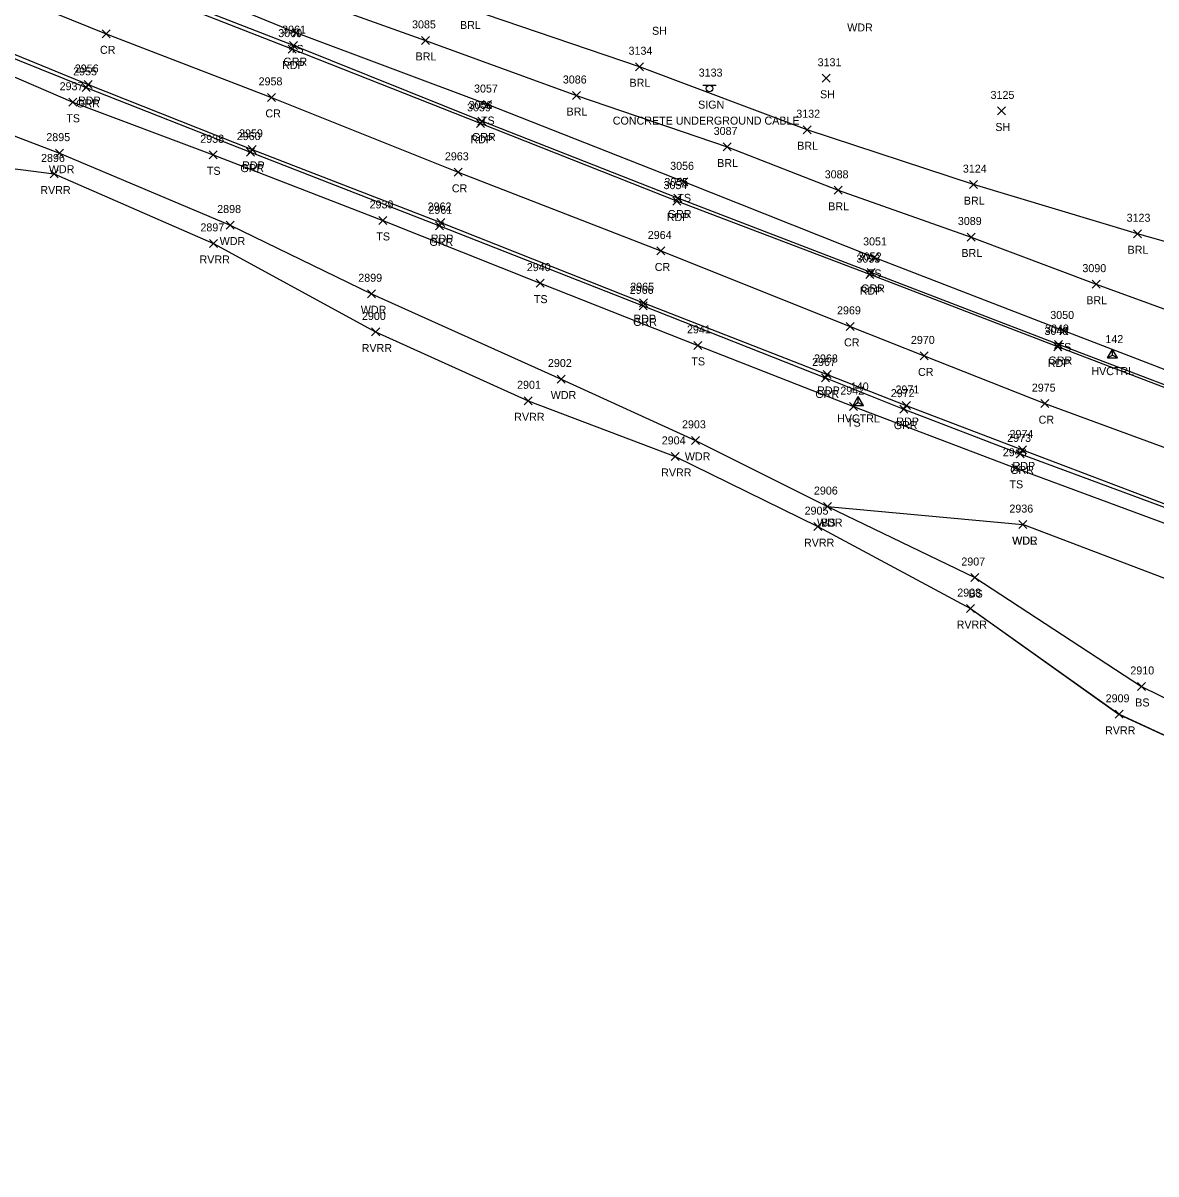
# Model space of a CAD drawing. Extents: x 1599569 to 1610055, y 642560 to 647860.
# Drawn here: x 1600521.5 to 1600804.5, y 647172.4 to 647459.9 of the extents above; entities that cross this region are included whole.
import ezdxf

# ---------------------------------------------------------------- set-up
doc = ezdxf.new("R2010")
doc.units = 0
for name, color, linetype in [('C_A', 7, 'Continuous'), ('C_I', 7, 'Continuous'), ('CPSM', 7, 'Continuous'), ('L_A', 7, 'Continuous'), ('L_I', 7, 'Continuous'), ('L_TIC', 7, 'Continuous'), ('LABL', 7, 'Continuous'), ('LAWA', 7, 'Continuous'), ('LAWE', 7, 'Continuous'), ('LELB', 7, 'Continuous'), ('LSOGP', 7, 'Continuous'), ('P_A', 7, 'Continuous'), ('P_I', 7, 'Continuous'), ('P_TIC', 7, 'Continuous'), ('PET', 7, 'Continuous'), ('PRC', 7, 'Continuous'), ('R_A', 7, 'Continuous'), ('R_I', 7, 'Continuous'), ('R_TIC', 7, 'Continuous'), ('RGR', 7, 'Continuous'), ('S_A', 7, 'Continuous'), ('S_C', 7, 'Continuous'), ('S_I', 7, 'Continuous'), ('SSGN', 7, 'Continuous')]:
    doc.layers.add(name, color=color, linetype=linetype)

msp = doc.modelspace()

# ---------------------------------------------------------------- linework, layer by layer
at = {"layer": 'CPSM'}
for p, q in [((1600792.39, 647376.21), (1600793.64, 647378.37)), ((1600794.89, 647376.21), (1600793.64, 647378.37)), ((1600793.64, 647376.93), (1600793.64, 647378.37)), ((1600792.39, 647376.21), (1600793.64, 647376.93)), ((1600792.39, 647376.21), (1600794.89, 647376.21)), ((1600793.64, 647376.93), (1600793.64, 647376.93)), ((1600793.64, 647376.93), (1600794.89, 647376.21)), ((1600728.89, 647364.38), (1600730.14, 647366.55)), ((1600728.89, 647364.38), (1600730.14, 647365.1)), ((1600728.89, 647364.38), (1600731.39, 647364.38)), ((1600731.39, 647364.38), (1600730.14, 647366.55)), ((1600730.14, 647365.1), (1600730.14, 647366.55)), ((1600730.14, 647365.1), (1600730.14, 647365.1)), ((1600730.14, 647365.1), (1600731.39, 647364.38))]:
    msp.add_line(p, q, dxfattribs=at)
at = {"layer": 'L_TIC'}
for points in [[(1600588.75, 647456.41), (1600590.75, 647458.41)], [(1600590.75, 647456.41), (1600588.75, 647458.41)], [(1600621.01, 647454.54), (1600623.01, 647456.54)], [(1600623.01, 647454.54), (1600621.01, 647456.54)], [(1600674.44, 647447.96), (1600676.44, 647449.96)], [(1600676.44, 647447.96), (1600674.44, 647449.96)], [(1600721.09, 647445.08), (1600723.09, 647447.08)], [(1600723.09, 647445.08), (1600721.09, 647447.08)], [(1600658.72, 647440.77), (1600660.72, 647442.77)], [(1600660.72, 647440.77), (1600658.72, 647442.77)], [(1600532.9, 647439.09), (1600534.9, 647441.09)], [(1600534.9, 647439.09), (1600532.9, 647441.09)], [(1600636.49, 647438.52), (1600638.49, 647440.52)], [(1600638.49, 647438.52), (1600636.49, 647440.52)], [(1600764.87, 647436.92), (1600766.87, 647438.92)], [(1600766.87, 647436.92), (1600764.87, 647438.92)], [(1600716.33, 647432.23), (1600718.33, 647434.23)], [(1600718.33, 647432.23), (1600716.33, 647434.23)], [(1600529.58, 647426.37), (1600531.58, 647428.37)], [(1600531.58, 647426.37), (1600529.58, 647428.37)], [(1600568.02, 647425.96), (1600570.02, 647427.96)], [(1600570.02, 647425.96), (1600568.02, 647427.96)], [(1600696.35, 647427.92), (1600698.35, 647429.92)], [(1600698.35, 647427.92), (1600696.35, 647429.92)], [(1600528.31, 647421.17), (1600530.31, 647423.17)], [(1600530.31, 647421.17), (1600528.31, 647423.17)], [(1600685.53, 647419.21), (1600687.53, 647421.21)], [(1600687.53, 647419.21), (1600685.53, 647421.21)], [(1600724.07, 647417.09), (1600726.07, 647419.09)], [(1600726.07, 647417.09), (1600724.07, 647419.09)], [(1600757.94, 647418.51), (1600759.94, 647420.51)], [(1600759.94, 647418.51), (1600757.94, 647420.51)], [(1600572.26, 647408.42), (1600574.26, 647410.42)], [(1600574.26, 647408.42), (1600572.26, 647410.42)], [(1600610.34, 647409.57), (1600612.34, 647411.57)], [(1600612.34, 647409.57), (1600610.34, 647411.57)], [(1600757.35, 647405.43), (1600759.35, 647407.43)], [(1600759.35, 647405.43), (1600757.35, 647407.43)], [(1600798.84, 647406.24), (1600800.84, 647408.24)], [(1600800.84, 647406.24), (1600798.84, 647408.24)], [(1600568.07, 647403.83), (1600570.07, 647405.83)], [(1600570.07, 647403.83), (1600568.07, 647405.83)], [(1600733.1, 647400.33), (1600735.1, 647402.33)], [(1600735.1, 647400.33), (1600733.1, 647402.33)], [(1600649.69, 647393.91), (1600651.69, 647395.91)], [(1600651.69, 647393.91), (1600649.69, 647395.91)], [(1600788.53, 647393.65), (1600790.53, 647395.65)], [(1600790.53, 647393.65), (1600788.53, 647395.65)], [(1600607.51, 647391.25), (1600609.51, 647393.25)], [(1600609.51, 647391.25), (1600607.51, 647393.25)], [(1600608.58, 647381.71), (1600610.58, 647383.71)], [(1600610.58, 647381.71), (1600608.58, 647383.71)], [(1600780.51, 647381.96), (1600782.51, 647383.96)], [(1600782.51, 647381.96), (1600780.51, 647383.96)], [(1600689.03, 647378.36), (1600691.03, 647380.36)], [(1600691.03, 647378.36), (1600689.03, 647380.36)], [(1600654.95, 647369.95), (1600656.95, 647371.95)], [(1600656.95, 647369.95), (1600654.95, 647371.95)], [(1600646.67, 647364.52), (1600648.67, 647366.52)], [(1600648.67, 647364.52), (1600646.67, 647366.52)], [(1600727.9, 647363.07), (1600729.9, 647365.07)], [(1600729.9, 647363.07), (1600727.9, 647365.07)], [(1600688.44, 647354.63), (1600690.44, 647356.63)], [(1600690.44, 647354.63), (1600688.44, 647356.63)], [(1600683.38, 647350.62), (1600685.38, 647352.62)], [(1600685.38, 647350.62), (1600683.38, 647352.62)], [(1600768.48, 647347.66), (1600770.48, 647349.66)], [(1600770.48, 647347.66), (1600768.48, 647349.66)], [(1600721.44, 647338.09), (1600723.44, 647340.09)], [(1600723.44, 647338.09), (1600721.44, 647340.09)], [(1600721.44, 647338.09), (1600723.44, 647340.09)], [(1600723.44, 647338.09), (1600721.44, 647340.09)], [(1600770.19, 647333.59), (1600772.19, 647335.59)], [(1600772.19, 647333.59), (1600770.19, 647335.59)], [(1600770.19, 647333.59), (1600772.19, 647335.59)], [(1600772.19, 647333.59), (1600770.19, 647335.59)], [(1600719.06, 647333.08), (1600721.06, 647335.08)], [(1600721.06, 647333.08), (1600719.06, 647335.08)], [(1600758.21, 647320.37), (1600760.21, 647322.37)], [(1600760.21, 647320.37), (1600758.21, 647322.37)], [(1600757.19, 647312.61), (1600759.19, 647314.61)], [(1600759.19, 647312.61), (1600757.19, 647314.61)], [(1600799.87, 647293.16), (1600801.87, 647295.16)], [(1600801.87, 647293.16), (1600799.87, 647295.16)], [(1600794.26, 647286.2), (1600796.26, 647288.2)], [(1600796.26, 647286.2), (1600794.26, 647288.2)]]:
    msp.add_lwpolyline(points, dxfattribs=at)
at = {"layer": 'LABL'}
msp.add_lwpolyline([(1600549.16, 647482.12), (1600587.34, 647468), (1600622.01, 647455.54), (1600659.72, 647441.77), (1600697.35, 647428.92), (1600725.07, 647418.09), (1600758.35, 647406.43), (1600789.53, 647394.65), (1600829.98, 647379.88), (1600858.93, 647365.17), (1600893.05, 647356.35), (1600928.59, 647369.58), (1600886.67, 647382.78), (1600843.57, 647394.9), (1600799.84, 647407.24), (1600758.94, 647419.51), (1600717.33, 647433.23), (1600675.44, 647448.96), (1600633.1, 647463.38), (1600594.68, 647476.25), (1600537.7, 647496.6)], dxfattribs=at)
at = {"layer": 'LAWA'}
for points in [[(1600386.94, 647428.55), (1600444.42, 647438.63), (1600497.01, 647440.19), (1600530.58, 647427.37), (1600573.26, 647409.42), (1600608.51, 647392.25), (1600655.95, 647370.95), (1600689.44, 647355.63), (1600722.44, 647339.09), (1600771.19, 647334.59)], [(1600826.18, 647313.68), (1600771.19, 647334.59)]]:
    msp.add_lwpolyline(points, dxfattribs=at)
at = {"layer": 'LAWE'}
msp.add_lwpolyline([(1600386.2, 647413.3), (1600443.74, 647417.36), (1600495.54, 647426.53), (1600529.31, 647422.17), (1600569.07, 647404.83), (1600609.58, 647382.71), (1600647.67, 647365.52), (1600684.38, 647351.62), (1600720.06, 647334.08), (1600758.19, 647313.61), (1600795.26, 647287.2), (1600825.21, 647273.44), (1600845.5, 647251.6), (1600858.85, 647232.88), (1600883.27, 647196.85), (1600913.08, 647172.38)], dxfattribs=at)
at = {"layer": 'LELB'}
for points in [[(1600055.84, 647629.73), (1600100.47, 647612.9), (1600146.77, 647594.54), (1600189.82, 647577.13), (1600237.92, 647558.86), (1600277.02, 647541.96), (1600322.78, 647524.01), (1600364.2, 647505.89), (1600375.48, 647498.79), (1600409.04, 647488.5), (1600456.88, 647470.52), (1600501.29, 647454.21), (1600533.9, 647440.09), (1600569.02, 647426.96), (1600611.34, 647410.57), (1600650.69, 647394.91), (1600690.03, 647379.36), (1600728.9, 647364.07), (1600769.48, 647348.66), (1600809.53, 647333.88)], [(1601065.14, 647298.7), (1601017.93, 647308.63), (1600970.12, 647319.08), (1600922.99, 647332.86), (1600876.04, 647347.67), (1600828.44, 647364.9), (1600781.51, 647382.96), (1600734.1, 647401.33), (1600686.53, 647420.21), (1600637.49, 647439.52), (1600589.75, 647457.41), (1600542.23, 647476.94), (1600495.72, 647495.2), (1600449.86, 647513.12), (1600405.19, 647531.59), (1600383.83, 647541.02), (1600357.09, 647550.14)], [(1600722.44, 647339.09), (1600759.21, 647321.37), (1600800.87, 647294.16), (1600827.82, 647280.95), (1600853.87, 647269.44), (1600873.75, 647258.18), (1600911.21, 647242.33), (1600935.02, 647233.32), (1600949.35, 647228.64)]]:
    msp.add_lwpolyline(points, dxfattribs=at)
at = {"layer": 'LSOGP'}
msp.add_lwpolyline([(1600070.65, 647558.33), (1600121.43, 647538.97), (1600161.93, 647520.51), (1600212, 647501.45), (1600250.01, 647482.64), (1600296.6, 647464.05), (1600337.09, 647450.04), (1600386.21, 647413.3), (1600443.74, 647417.36), (1600495.54, 647426.53), (1600529.31, 647422.18), (1600569.07, 647404.83), (1600609.57, 647382.72), (1600647.67, 647365.52), (1600684.38, 647351.62), (1600720.06, 647334.08), (1600758.19, 647313.6), (1600795.26, 647287.19), (1600825.21, 647273.44)], dxfattribs=at)
at = {"layer": 'P_TIC'}
for points in [[(1600541.28, 647456.18), (1600543.28, 647458.18)], [(1600543.28, 647456.18), (1600541.28, 647458.18)], [(1600587.71, 647452.36), (1600589.71, 647454.36)], [(1600589.71, 647452.36), (1600587.71, 647454.36)], [(1600536.74, 647443.52), (1600538.74, 647445.52)], [(1600538.74, 647443.52), (1600536.74, 647445.52)], [(1600582.6, 647440.31), (1600584.6, 647442.31)], [(1600584.6, 647440.31), (1600582.6, 647442.31)], [(1600634.75, 647433.82), (1600636.75, 647435.82)], [(1600636.75, 647433.82), (1600634.75, 647435.82)], [(1600577.73, 647427.32), (1600579.73, 647429.32)], [(1600579.73, 647427.32), (1600577.73, 647429.32)], [(1600629.18, 647421.59), (1600631.18, 647423.59)], [(1600631.18, 647421.59), (1600629.18, 647423.59)], [(1600683.81, 647414.39), (1600685.81, 647416.39)], [(1600685.81, 647414.39), (1600683.81, 647416.39)], [(1600624.87, 647409.05), (1600626.87, 647411.05)], [(1600626.87, 647409.05), (1600624.87, 647411.05)], [(1600679.85, 647401.94), (1600681.85, 647403.94)], [(1600681.85, 647401.94), (1600679.85, 647403.94)], [(1600732.01, 647396.03), (1600734.01, 647398.03)], [(1600734.01, 647396.03), (1600732.01, 647398.03)], [(1600675.47, 647389.02), (1600677.47, 647391.02)], [(1600677.47, 647389.02), (1600675.47, 647391.02)], [(1600727.14, 647383.11), (1600729.14, 647385.11)], [(1600729.14, 647383.11), (1600727.14, 647385.11)], [(1600778.98, 647377.97), (1600780.98, 647379.97)], [(1600780.98, 647377.97), (1600778.98, 647379.97)], [(1600745.62, 647375.72), (1600747.62, 647377.72)], [(1600747.62, 647375.72), (1600745.62, 647377.72)], [(1600721.37, 647371.09), (1600723.37, 647373.09)], [(1600723.37, 647371.09), (1600721.37, 647373.09)], [(1600741.13, 647363.34), (1600743.13, 647365.34)], [(1600743.13, 647363.34), (1600741.13, 647365.34)], [(1600775.73, 647363.8), (1600777.73, 647365.8)], [(1600777.73, 647363.8), (1600775.73, 647365.8)], [(1600770.17, 647352.24), (1600772.17, 647354.24)], [(1600772.17, 647352.24), (1600770.17, 647354.24)]]:
    msp.add_lwpolyline(points, dxfattribs=at)
at = {"layer": 'PET'}
for points in [[(1600057, 647632.55), (1600100.87, 647615.07), (1600147.9, 647596.67), (1600191.15, 647579.83), (1600239.1, 647561.25), (1600278.32, 647545.78), (1600324.18, 647528.07), (1600366.68, 647511.17), (1600410.28, 647494.24), (1600458.68, 647475.59), (1600502.98, 647458.78), (1600537.74, 647444.52), (1600578.73, 647428.32), (1600625.87, 647410.05), (1600676.47, 647390.02), (1600722.37, 647372.09), (1600742.13, 647364.34), (1600771.17, 647353.24), (1600818.96, 647335.1)], [(1600827.68, 647360.8), (1600779.98, 647378.97), (1600733.01, 647397.03), (1600684.81, 647415.39), (1600635.75, 647434.82), (1600588.71, 647453.36), (1600540.53, 647472.21), (1600493.83, 647490.9), (1600448.1, 647508.92), (1600403.13, 647526.81), (1600379.45, 647536), (1600354.99, 647546.03)]]:
    msp.add_lwpolyline(points, dxfattribs=at)
at = {"layer": 'PRC'}
msp.add_lwpolyline([(1600061.65, 647646.14), (1600106.08, 647628.64), (1600153.61, 647610.06), (1600197.14, 647593.63), (1600244.86, 647574.99), (1600283.53, 647559.51), (1600330.13, 647541.37), (1600373.85, 647524.01), (1600415.89, 647507.43), (1600464.39, 647488.21), (1600507.95, 647471.08), (1600542.28, 647457.18), (1600583.6, 647441.31), (1600630.18, 647422.59), (1600680.85, 647402.94), (1600728.14, 647384.11), (1600746.62, 647376.72), (1600776.73, 647364.8), (1600822.54, 647348.05)], dxfattribs=at)
at = {"layer": 'R_TIC'}
for points in [[(1600588.04, 647453.23), (1600590.04, 647455.23)], [(1600590.04, 647453.23), (1600588.04, 647455.23)], [(1600536.28, 647442.8), (1600538.28, 647444.8)], [(1600538.28, 647442.8), (1600536.28, 647444.8)], [(1600635.13, 647434.4), (1600637.13, 647436.4)], [(1600637.13, 647434.4), (1600635.13, 647436.4)], [(1600577.29, 647426.64), (1600579.29, 647428.64)], [(1600579.29, 647426.64), (1600577.29, 647428.64)], [(1600684.04, 647415.17), (1600686.04, 647417.17)], [(1600686.04, 647415.17), (1600684.04, 647417.17)], [(1600624.5, 647408.22), (1600626.5, 647410.22)], [(1600626.5, 647408.22), (1600624.5, 647410.22)], [(1600732.34, 647396.57), (1600734.34, 647398.57)], [(1600734.34, 647396.57), (1600732.34, 647398.57)], [(1600675.4, 647388.23), (1600677.4, 647390.23)], [(1600677.4, 647388.23), (1600675.4, 647390.23)], [(1600779.14, 647378.57), (1600781.14, 647380.57)], [(1600781.14, 647378.57), (1600779.14, 647380.57)], [(1600720.9, 647370.23), (1600722.9, 647372.23)], [(1600722.9, 647370.23), (1600720.9, 647372.23)], [(1600740.51, 647362.43), (1600742.51, 647364.43)], [(1600742.51, 647362.43), (1600740.51, 647364.43)], [(1600769.59, 647351.25), (1600771.59, 647353.25)], [(1600771.59, 647351.25), (1600769.59, 647353.25)]]:
    msp.add_lwpolyline(points, dxfattribs=at)
at = {"layer": 'RGR'}
for points in [[(1601112.7, 647287.9), (1601065.04, 647296.19), (1601016.91, 647305.01), (1600969.35, 647316.03), (1600921.82, 647329.78), (1600875.51, 647344.39), (1600827.81, 647361.39), (1600780.14, 647379.57), (1600733.34, 647397.57), (1600685.04, 647416.17), (1600636.13, 647435.4), (1600589.04, 647454.23), (1600540.52, 647473.18), (1600494.45, 647491.58), (1600448.44, 647509.99), (1600404.22, 647528.66), (1600382.85, 647539.14)], [(1600375.92, 647501.33), (1600409.75, 647491.68), (1600457.98, 647474.45), (1600502.92, 647457.62), (1600537.28, 647443.8), (1600578.29, 647427.64), (1600625.5, 647409.22), (1600676.4, 647389.23), (1600721.9, 647371.23), (1600741.51, 647363.43), (1600770.59, 647352.25), (1600818.71, 647334.42), (1600868.72, 647316.7), (1600918.16, 647301.27), (1600965.58, 647287.14), (1601011.99, 647275.75), (1601059.57, 647265), (1601100.83, 647257.3), (1601109.97, 647255.84)]]:
    msp.add_lwpolyline(points, dxfattribs=at)
at = {"layer": 'SSGN'}
for p, q in [((1600691.33, 647444.36), (1600694.67, 647444.36)), ((1600692.98, 647443.52), (1600692.98, 647443.52))]:
    msp.add_line(p, q, dxfattribs=at)
msp.add_circle((1600692.98, 647443.52), 0.833, dxfattribs=at)

# ---------------------------------------------------------------- texts
at = {"layer": 'C_A'}
for p in [(1600788.34, 647371.93), (1600724.83, 647360.1)]:
    msp.add_text('HVCTRL', height=2, dxfattribs=at).set_placement(p)
at = {"layer": 'C_I'}
for s, p in [('142', (1600791.85, 647379.93)), ('140', (1600728.26, 647368.1))]:
    msp.add_text(s, height=2, dxfattribs=at).set_placement(p)
at = {"layer": 'L_A'}
for s, p in [('BRL', (1600630.65, 647458.38)), ('SH', (1600678.6, 647456.94)), ('WDR', (1600727.36, 647457.77)), ('TS', (1600588.16, 647452.41)), ('BRL', (1600619.55, 647450.54)), ('BRL', (1600672.98, 647443.96)), ('SH', (1600720.58, 647441.08)), ('BRL', (1600657.26, 647436.77)), ('TS', (1600532.31, 647435.09)), ('TS', (1600635.89, 647434.52)), ('SH', (1600764.36, 647432.92)), ('BRL', (1600714.87, 647428.23)), ('WDR', (1600527.94, 647422.37)), ('BRL', (1600694.89, 647423.92)), ('TS', (1600567.43, 647421.96)), ('RVRR', (1600525.82, 647417.17)), ('TS', (1600684.94, 647415.21)), ('BRL', (1600756.49, 647414.51)), ('BRL', (1600722.62, 647413.09)), ('TS', (1600609.75, 647405.57)), ('WDR', (1600570.62, 647404.42)), ('RVRR', (1600565.58, 647399.83)), ('BRL', (1600755.89, 647401.43)), ('BRL', (1600797.39, 647402.24)), ('TS', (1600732.51, 647396.33)), ('TS', (1600649.1, 647389.91)), ('BRL', (1600787.08, 647389.65)), ('WDR', (1600605.87, 647387.25)), ('RVRR', (1600606.09, 647377.71)), ('TS', (1600779.92, 647377.96)), ('TS', (1600688.44, 647374.36)), ('WDR', (1600653.31, 647365.95)), ('RVRR', (1600644.19, 647360.52)), ('TS', (1600727.31, 647359.07)), ('WDR', (1600686.8, 647350.63)), ('RVRR', (1600680.89, 647346.62)), ('TS', (1600767.89, 647343.66)), ('WDR', (1600719.81, 647334.09)), ('BS', (1600720.88, 647334.09)), ('RVRR', (1600716.57, 647329.08)), ('WDR', (1600768.55, 647329.59)), ('WDL', (1600768.6, 647329.59)), ('BS', (1600757.65, 647316.37)), ('RVRR', (1600754.7, 647308.61)), ('BS', (1600799.31, 647289.16)), ('RVRR', (1600791.77, 647282.2))]:
    msp.add_text(s, height=2, dxfattribs=at).set_placement(p)
at = {"layer": 'L_I'}
for s, p in [('3085', (1600618.67, 647458.54)), ('3134', (1600672.75, 647451.96)), ('3131', (1600719.97, 647449.08)), ('2937', (1600530.64, 647443.09)), ('3057', (1600634.15, 647442.52)), ('3086', (1600656.33, 647444.77)), ('3125', (1600763.17, 647440.92)), ('3132', (1600714.64, 647436.23)), ('3087', (1600694.01, 647431.92)), ('2895', (1600527.32, 647430.37)), ('2938', (1600565.76, 647429.96)), ('2896', (1600526, 647425.17)), ('3056', (1600683.14, 647423.21)), ('3124', (1600756.25, 647422.51)), ('3088', (1600721.74, 647421.09)), ('2898', (1600570, 647412.42)), ('2939', (1600608.07, 647413.57)), ('3089', (1600755, 647409.43)), ('3123', (1600797.15, 647410.24)), ('2897', (1600565.81, 647407.83)), ('3051', (1600731.33, 647404.33)), ('2940', (1600647.34, 647397.91)), ('3090', (1600786.11, 647397.65)), ('2899', (1600605.24, 647395.25)), ('2900', (1600606.15, 647385.71)), ('3050', (1600778.08, 647385.96)), ('2941', (1600687.34, 647382.36)), ('2902', (1600652.61, 647373.95)), ('2901', (1600644.9, 647368.52)), ('2942', (1600725.64, 647367.07)), ('2903', (1600686.1, 647358.63)), ('2904', (1600681.04, 647354.62)), ('2943', (1600766.22, 647351.66)), ('2906', (1600719.05, 647342.09)), ('2906', (1600719.05, 647342.09)), ('2905', (1600716.72, 647337.08)), ('2936', (1600767.87, 647337.59)), ('2936', (1600767.87, 647337.59)), ('2907', (1600755.87, 647324.37)), ('2908', (1600754.85, 647316.61)), ('2910', (1600798.09, 647297.16)), ('2909', (1600791.92, 647290.2))]:
    msp.add_text(s, height=2, dxfattribs=at).set_placement(p)
at = {"layer": 'P_A'}
for s, p in [('CR', (1600540.71, 647452.18)), ('RDP', (1600586.2, 647448.36)), ('RDP', (1600535.23, 647439.52)), ('CR', (1600582.04, 647436.31)), ('RDP', (1600633.24, 647429.82)), ('RDP', (1600576.22, 647423.32)), ('CR', (1600628.61, 647417.59)), ('RDP', (1600682.3, 647410.39)), ('RDP', (1600623.35, 647405.05)), ('CR', (1600679.29, 647397.94)), ('RDP', (1600730.49, 647392.03)), ('RDP', (1600673.96, 647385.02)), ('CR', (1600726.57, 647379.11)), ('RDP', (1600777.47, 647373.97)), ('CR', (1600745.05, 647371.72)), ('RDP', (1600719.86, 647367.09)), ('RDP', (1600739.62, 647359.34)), ('CR', (1600775.17, 647359.8)), ('RDP', (1600768.66, 647348.24))]:
    msp.add_text(s, height=2, dxfattribs=at).set_placement(p)
at = {"layer": 'P_I'}
for s, p in [('3060', (1600585.24, 647456.36)), ('2956', (1600534.43, 647447.52)), ('2958', (1600580.34, 647444.31)), ('3059', (1600632.41, 647437.82)), ('2959', (1600575.46, 647431.32)), ('2963', (1600626.87, 647425.59)), ('3054', (1600681.48, 647418.39)), ('2962', (1600622.56, 647413.05)), ('2964', (1600677.55, 647405.94)), ('3053', (1600729.67, 647400.03)), ('2965', (1600673.17, 647393.02)), ('2969', (1600724.82, 647387.11)), ('2970', (1600743.27, 647379.72)), ('3048', (1600776.64, 647381.97)), ('2968', (1600719.07, 647375.09)), ('2975', (1600773.47, 647367.8)), ('2971', (1600739.43, 647367.34)), ('2974', (1600767.91, 647356.24))]:
    msp.add_text(s, height=2, dxfattribs=at).set_placement(p)
at = {"layer": 'R_A'}
for p in [(1600586.53, 647449.23), (1600534.77, 647438.8), (1600633.62, 647430.4), (1600575.78, 647422.64), (1600682.53, 647411.17), (1600622.99, 647404.22), (1600730.83, 647392.57), (1600673.89, 647384.23), (1600777.63, 647374.57), (1600719.39, 647366.23), (1600739, 647358.43), (1600768.08, 647347.25)]:
    msp.add_text('GRR', height=2, dxfattribs=at).set_placement(p)
at = {"layer": 'R_I'}
for s, p in [('3061', (1600586.22, 647457.23)), ('2955', (1600534.02, 647446.8)), ('3058', (1600632.79, 647438.4)), ('2960', (1600574.9, 647430.64)), ('3055', (1600681.7, 647419.17)), ('2961', (1600622.76, 647412.22)), ('3052', (1600730, 647400.57)), ('2966', (1600673.04, 647392.23)), ('3049', (1600776.79, 647382.57)), ('2967', (1600718.6, 647374.23)), ('2972', (1600738.25, 647366.43)), ('2973', (1600767.33, 647355.25))]:
    msp.add_text(s, height=2, dxfattribs=at).set_placement(p)
at = {"layer": 'S_A'}
msp.add_text('SIGN', height=2, dxfattribs=at).set_placement((1600690.12, 647438.5))
at = {"layer": 'S_C'}
msp.add_text('CONCRETE UNDERGROUND CABLE', height=2, dxfattribs=at).set_placement((1600668.8, 647434.5))
at = {"layer": 'S_I'}
msp.add_text('3133', height=2, dxfattribs=at).set_placement((1600690.27, 647446.5))

doc.saveas('drawing.dxf')
